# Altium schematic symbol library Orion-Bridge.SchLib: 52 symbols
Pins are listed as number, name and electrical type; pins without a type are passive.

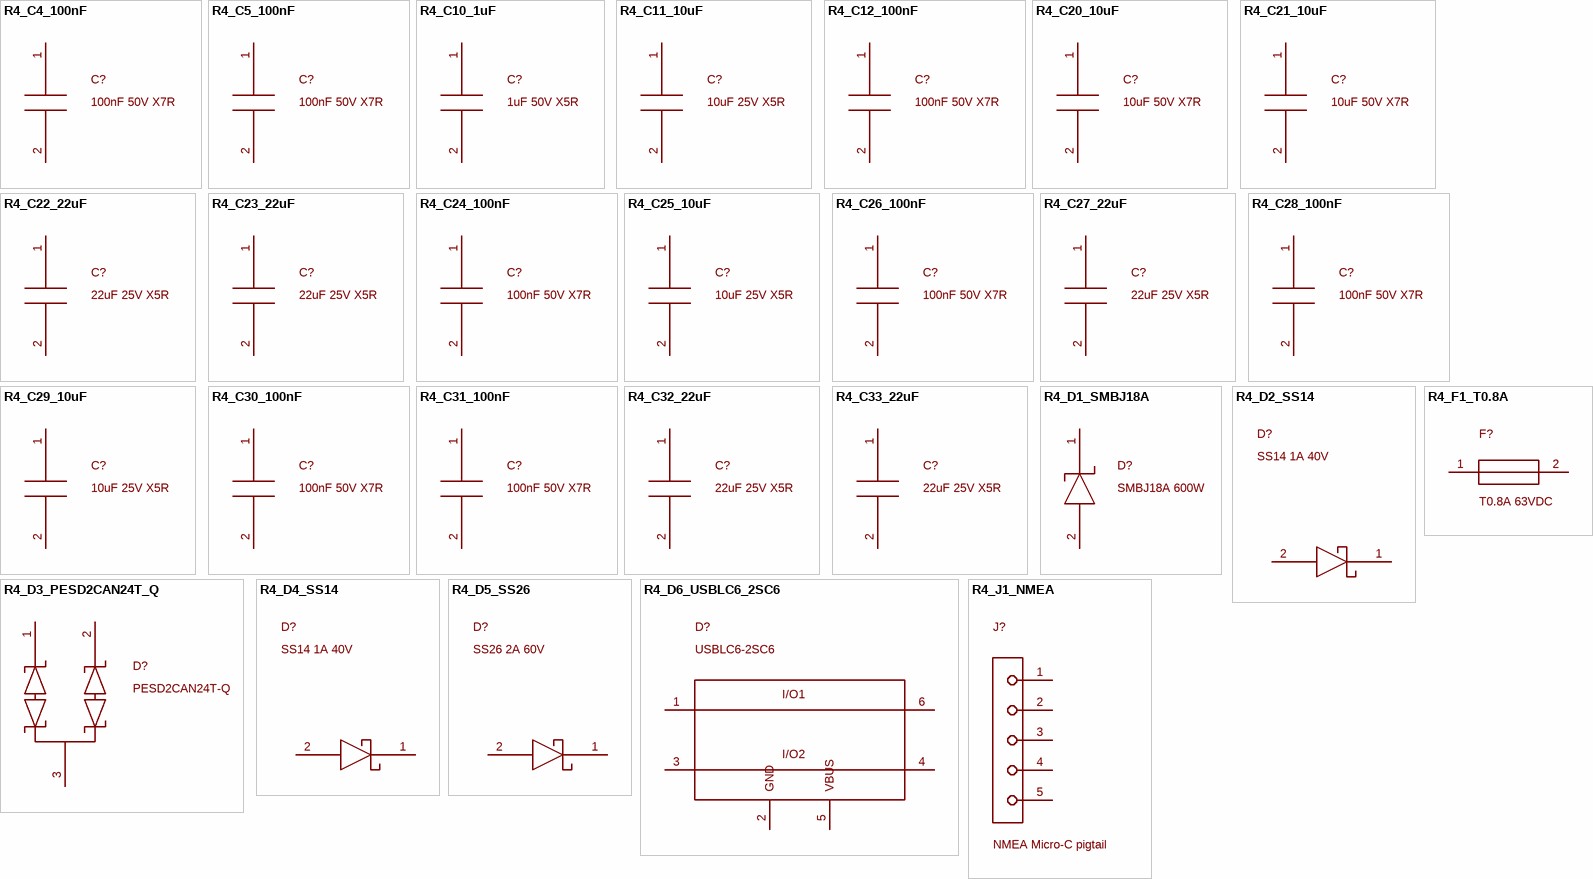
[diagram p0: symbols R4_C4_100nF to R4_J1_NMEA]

## R4_C4_100nF
designator C?, comment 100nF 50V X7R
100nF 16V X7R - generic specification; manufacturer/MPN not selected; Manufacturer: YAGEO; MPN: CC0603KRX7R9BB104
footprint C0603
pins: 1, 2

## R4_C5_100nF
designator C?, comment 100nF 50V X7R
100nF 16V X7R - generic specification; manufacturer/MPN not selected; Manufacturer: YAGEO; MPN: CC0603KRX7R9BB104
footprint C0603
pins: 1, 2

## R4_C10_1uF
designator C?, comment 1uF 50V X5R
Manufacturer: Samsung Electro-Mechanics; MPN: CL10A105KB8NNNC
footprint C0603
pins: 1, 2

## R4_C11_10uF
designator C?, comment 10uF 25V X5R
Manufacturer: Samsung Electro-Mechanics; MPN: CL21A106KAYNNNE
footprint C0805
pins: 1, 2

## R4_C12_100nF
designator C?, comment 100nF 50V X7R
Manufacturer: YAGEO; MPN: CC0603KRX7R9BB104
footprint C0603
pins: 1, 2

## R4_C20_10uF
designator C?, comment 10uF 50V X7R
Manufacturer: Samsung Electro-Mechanics; MPN: CL32B106KBJNNNE
footprint C1210
pins: 1, 2

## R4_C21_10uF
designator C?, comment 10uF 50V X7R
Manufacturer: Samsung Electro-Mechanics; MPN: CL32B106KBJNNNE
footprint C1210
pins: 1, 2

## R4_C22_22uF
designator C?, comment 22uF 25V X5R
Manufacturer: Samsung Electro-Mechanics; MPN: CL31A226KAHNNNE
footprint C1206
pins: 1, 2

## R4_C23_22uF
designator C?, comment 22uF 25V X5R
Manufacturer: Samsung Electro-Mechanics; MPN: CL31A226KAHNNNE
footprint C1206
pins: 1, 2

## R4_C24_100nF
designator C?, comment 100nF 50V X7R
Manufacturer: YAGEO; MPN: CC0603KRX7R9BB104
footprint C0603
pins: 1, 2

## R4_C25_10uF
designator C?, comment 10uF 25V X5R
Manufacturer: Samsung Electro-Mechanics; MPN: CL21A106KAYNNNE
footprint C0805
pins: 1, 2

## R4_C26_100nF
designator C?, comment 100nF 50V X7R
Manufacturer: YAGEO; MPN: CC0603KRX7R9BB104
footprint C0603
pins: 1, 2

## R4_C27_22uF
designator C?, comment 22uF 25V X5R
Manufacturer: Samsung Electro-Mechanics; MPN: CL31A226KAHNNNE
footprint C1206
pins: 1, 2

## R4_C28_100nF
designator C?, comment 100nF 50V X7R
Manufacturer: YAGEO; MPN: CC0603KRX7R9BB104
footprint C0603
pins: 1, 2

## R4_C29_10uF
designator C?, comment 10uF 25V X5R
Manufacturer: Samsung Electro-Mechanics; MPN: CL21A106KAYNNNE
footprint C0805
pins: 1, 2

## R4_C30_100nF
designator C?, comment 100nF 50V X7R
Manufacturer: YAGEO; MPN: CC0603KRX7R9BB104
footprint C0603
pins: 1, 2

## R4_C31_100nF
designator C?, comment 100nF 50V X7R
Manufacturer: YAGEO; MPN: CC0603KRX7R9BB104
footprint C0603
pins: 1, 2

## R4_C32_22uF
designator C?, comment 22uF 25V X5R
Manufacturer: Samsung Electro-Mechanics; MPN: CL31A226KAHNNNE
footprint C1206
pins: 1, 2

## R4_C33_22uF
designator C?, comment 22uF 25V X5R
Manufacturer: Samsung Electro-Mechanics; MPN: CL31A226KAHNNNE
footprint C1206
pins: 1, 2

## R4_D1_SMBJ18A
designator D?, comment SMBJ18A 600W
Manufacturer: BORN
footprint SMB
pins: 1 K, 2 A

## R4_D2_SS14
designator D?, comment SS14 1A 40V
Manufacturer: MDD(Microdiode Semiconductor)
footprint SMA
pins: 1 K, 2 A

## R4_D3_PESD2CAN24T_Q
designator D?, comment PESD2CAN24T-Q
Manufacturer: Nexperia; MPN: PESD2CAN24T-QR
footprint SOT23_NEXPERIA_REFLOW
pins: 1 K1, 2 K2, 3 CC

## R4_D4_SS14
designator D?, comment SS14 1A 40V
Manufacturer: MDD(Microdiode Semiconductor)
footprint SMA
pins: 1 K, 2 A

## R4_D5_SS26
designator D?, comment SS26 2A 60V
Manufacturer: MDD(Microdiode Semiconductor)
footprint SMA
pins: 1 K, 2 A

## R4_D6_USBLC6_2SC6
designator D?, comment USBLC6-2SC6
Manufacturer: STMicroelectronics
footprint SOT23_6_ST_USBLC6
pins: 1 IO1, 2 GND, 3 IO2, 4 IO2, 5 VBUS, 6 IO1

## R4_F1_T0.8A
designator F?, comment T0.8A 63VDC
0.8 A slow-blow SMD ceramic fuse, 63 VDC, 50 A interrupt rating; Manufacturer: BOURNS; MPN: SF-1206S080-2
footprint BOURNS_SF1206S
pins: 1, 2

## R4_J1_NMEA
designator J?, comment NMEA Micro-C pigtail
Five direct wire-solder pads for a separately selected Micro-C cable; this is a PCB interface, not an invented connector MPN or face view
footprint PIGTAIL_5_P3_D1P3
pins: 1 SHIELD, 2 NET-S, 3 NET-C, 4 CAN-H, 5 CAN-L

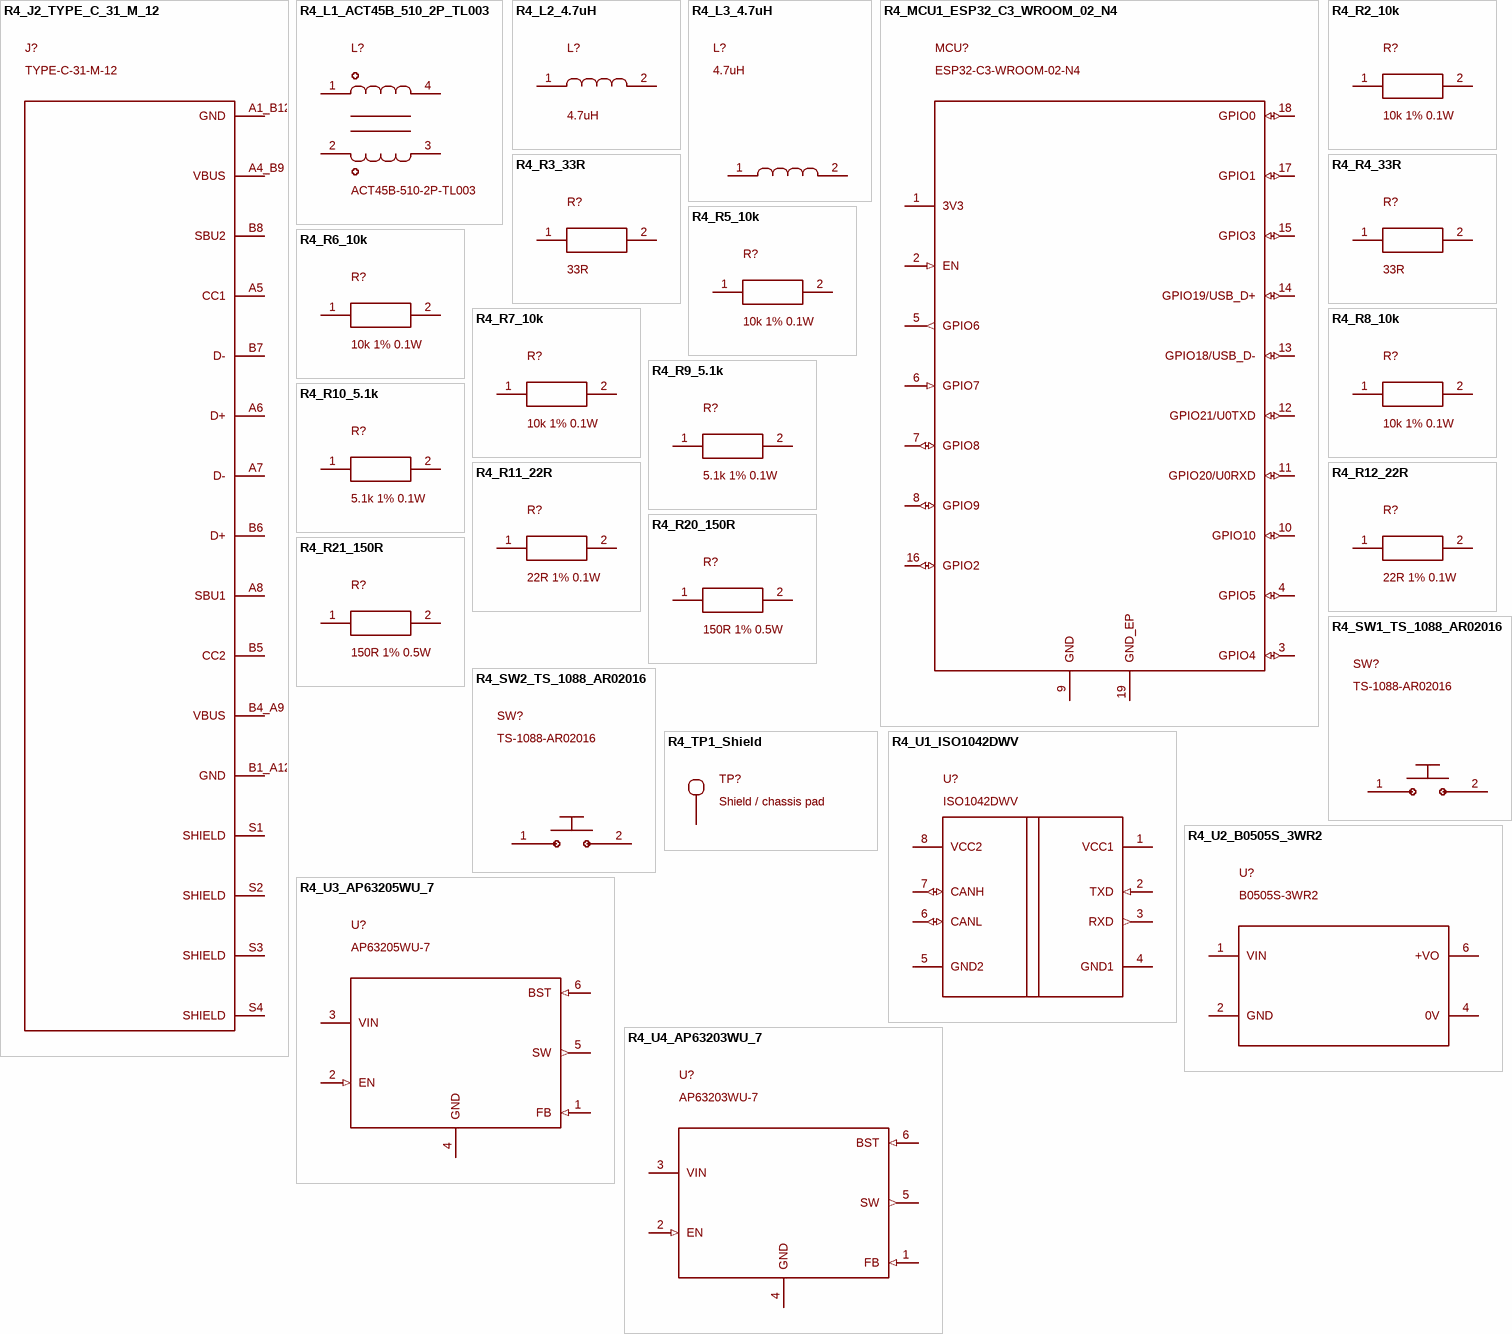
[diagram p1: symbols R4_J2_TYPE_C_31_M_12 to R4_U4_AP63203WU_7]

## R4_J2_TYPE_C_31_M_12
designator J?, comment TYPE-C-31-M-12
Manufacturer: Korean Hroparts Elec
footprint USB_C_HRO_TYPE_C_31_M_12_2020
pins: A1_B12 GND, A4_B9 VBUS, A5 CC1, A6 D+, A7 D-, A8 SBU1, B1_A12 GND, B4_A9 VBUS, B5 CC2, B6 D+, B7 D-, B8 SBU2, S1 SHIELD, S2 SHIELD, S3 SHIELD, S4 SHIELD

## R4_L1_ACT45B_510_2P_TL003
designator L?, comment ACT45B-510-2P-TL003
Manufacturer: TDK
footprint ACT45B
pins: 1 H_EXT, 2 L_EXT, 3 L_IC, 4 H_IC

## R4_L2_4.7uH
designator L?, comment 4.7uH
Manufacturer: Sunlord; MPN: SWPA4030S4R7MT
footprint SUNLORD_SWPA4030
pins: 1, 2

## R4_L3_4.7uH
designator L?, comment 4.7uH
Manufacturer: Sunlord; MPN: SWPA4030S4R7MT
footprint SUNLORD_SWPA4030
pins: 1, 2

## R4_MCU1_ESP32_C3_WROOM_02_N4
designator MCU?, comment ESP32-C3-WROOM-02-N4
Manufacturer: Espressif Systems
footprint ESP32_C3_WROOM_02
pins: 1 3V3 (power), 2 EN (in), 3 GPIO4 (io), 4 GPIO5 (io), 5 GPIO6 (out), 6 GPIO7 (in), 7 GPIO8 (io), 8 GPIO9 (io), 9 GND (power), 10 GPIO10 (io), 11 GPIO20/U0RXD (io), 12 GPIO21/U0TXD (io), 13 GPIO18/USB_D- (io), 14 GPIO19/USB_D+ (io), 15 GPIO3 (io), 16 GPIO2 (io), 17 GPIO1 (io), 18 GPIO0 (io), 19 GND_EP (power)

## R4_R2_10k
designator R?, comment 10k 1% 0.1W
10k - generic specification; manufacturer/MPN not selected; Manufacturer: UNI-ROYAL(Uniroyal Elec); MPN: 0603WAF1002T5E
footprint R0603
pins: 1, 2

## R4_R3_33R
designator R?, comment 33R
33R - generic specification; manufacturer/MPN not selected; Manufacturer: UNI-ROYAL(Uniroyal Elec); MPN: 0603WAF330JT5E
footprint R0603
pins: 1, 2

## R4_R4_33R
designator R?, comment 33R
33R - generic specification; manufacturer/MPN not selected; Manufacturer: UNI-ROYAL(Uniroyal Elec); MPN: 0603WAF330JT5E
footprint R0603
pins: 1, 2

## R4_R5_10k
designator R?, comment 10k 1% 0.1W
Manufacturer: UNI-ROYAL(Uniroyal Elec); MPN: 0603WAF1002T5E
footprint R0603
pins: 1, 2

## R4_R6_10k
designator R?, comment 10k 1% 0.1W
Manufacturer: UNI-ROYAL(Uniroyal Elec); MPN: 0603WAF1002T5E
footprint R0603
pins: 1, 2

## R4_R7_10k
designator R?, comment 10k 1% 0.1W
Manufacturer: UNI-ROYAL(Uniroyal Elec); MPN: 0603WAF1002T5E
footprint R0603
pins: 1, 2

## R4_R8_10k
designator R?, comment 10k 1% 0.1W
Manufacturer: UNI-ROYAL(Uniroyal Elec); MPN: 0603WAF1002T5E
footprint R0603
pins: 1, 2

## R4_R9_5.1k
designator R?, comment 5.1k 1% 0.1W
Manufacturer: UNI-ROYAL(Uniroyal Elec); MPN: 0603WAF5101T5E
footprint R0603
pins: 1, 2

## R4_R10_5.1k
designator R?, comment 5.1k 1% 0.1W
Manufacturer: UNI-ROYAL(Uniroyal Elec); MPN: 0603WAF5101T5E
footprint R0603
pins: 1, 2

## R4_R11_22R
designator R?, comment 22R 1% 0.1W
Manufacturer: UNI-ROYAL(Uniroyal Elec); MPN: 0603WAF220JT5E
footprint R0603
pins: 1, 2

## R4_R12_22R
designator R?, comment 22R 1% 0.1W
Manufacturer: UNI-ROYAL(Uniroyal Elec); MPN: 0603WAF220JT5E
footprint R0603
pins: 1, 2

## R4_R20_150R
designator R?, comment 150R 1% 0.5W
Manufacturer: SEI(Stackpole Elec); MPN: RNCP1206FTD150R
footprint R1206
pins: 1, 2

## R4_R21_150R
designator R?, comment 150R 1% 0.5W
Manufacturer: SEI(Stackpole Elec); MPN: RNCP1206FTD150R
footprint R1206
pins: 1, 2

## R4_SW1_TS_1088_AR02016
designator SW?, comment TS-1088-AR02016
Manufacturer: XUNPU
footprint SW_XUNPU_TS1088_AR
pins: 1 A, 2 B

## R4_SW2_TS_1088_AR02016
designator SW?, comment TS-1088-AR02016
Manufacturer: XUNPU
footprint SW_XUNPU_TS1088_AR
pins: 1 A, 2 B

## R4_TP1_Shield
designator TP?, comment Shield / chassis pad
Shield / chassis pad - generic specification; manufacturer/MPN not selected
footprint TESTPOINT_2MM
pins: 1 SHIELD

## R4_U1_ISO1042DWV
designator U?, comment ISO1042DWV
Manufacturer: Texas Instruments; MPN: ISO1042DWVR
footprint SOIC8_DWV
pins: 1 VCC1 (power), 2 TXD (in), 3 RXD (out), 4 GND1 (power), 5 GND2 (power), 6 CANL (io), 7 CANH (io), 8 VCC2 (power)

## R4_U2_B0505S_3WR2
designator U?, comment B0505S-3WR2
Manufacturer: EVISUN
footprint EVISUN_B0505S_3WR2
pins: 1 VIN (power), 2 GND (power), 4 0V (power), 6 +VO (power)

## R4_U3_AP63205WU_7
designator U?, comment AP63205WU-7
Manufacturer: Diodes Incorporated
footprint TSOT26_DIODES
pins: 1 FB (in), 2 EN (in), 3 VIN (power), 4 GND (power), 5 SW (out), 6 BST (in)

## R4_U4_AP63203WU_7
designator U?, comment AP63203WU-7
Manufacturer: Diodes Incorporated
footprint TSOT26_DIODES
pins: 1 FB (in), 2 EN (in), 3 VIN (power), 4 GND (power), 5 SW (out), 6 BST (in)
